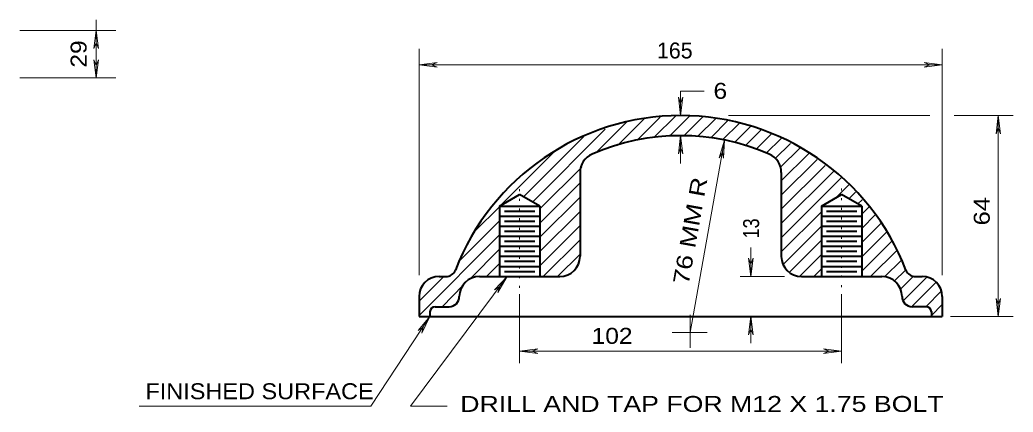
# Model space of a CAD drawing. Extents: x 312583 to 312853, y 144419 to 144586.
# Drawn here: x 312716.88 to 312764.18, y 144532.45 to 144551.14 of the extents above; entities that cross this region are included whole.
import ezdxf

# ---------------------------------------------------------------- set-up
doc = ezdxf.new("R2010")
doc.units = 0
doc.header["$LTSCALE"] = 0.3
doc.linetypes.add('DOTTED', pattern=[1.5, 0.3, -1.2])
doc.layers.add('1', color=7, linetype='Continuous', lineweight=40)
doc.layers.add('2', color=7, linetype='Continuous', lineweight=13)

msp = doc.modelspace()

# ---------------------------------------------------------------- linework, layer by layer
at = {"layer": '1'}
for p, q in [((312743.5539, 144543.8639), (312743.5539, 144539.8773)), ((312753.1372, 144543.8639), (312753.1372, 144539.8773)), ((312739.7205, 144542.2693), (312740.6789, 144542.8213)), ((312741.6372, 144542.2693), (312740.6789, 144542.8213)), ((312755.0539, 144542.2693), (312756.0122, 144542.8213)), ((312756.9705, 144542.2693), (312756.0122, 144542.8213)), ((312739.7205, 144542.2693), (312739.7205, 144538.9189)), ((312739.7205, 144542.2693), (312741.6372, 144542.2693)), ((312741.6372, 144542.2693), (312741.6372, 144538.9189)), ((312755.0539, 144542.2693), (312755.0539, 144538.9189)), ((312755.0539, 144542.2693), (312756.9705, 144542.2693)), ((312756.9705, 144542.2693), (312756.9705, 144538.9189)), ((312739.7205, 144541.7939), (312741.6372, 144541.7939)), ((312739.9582, 144542.0316), (312741.3995, 144542.0316)), ((312755.0539, 144541.7939), (312756.9705, 144541.7939)), ((312755.2915, 144542.0316), (312756.7329, 144542.0316)), ((312739.7205, 144541.3109), (312741.6372, 144541.3109)), ((312739.9582, 144541.5563), (312741.3995, 144541.5563)), ((312755.0539, 144541.3109), (312756.9705, 144541.3109)), ((312755.2915, 144541.5563), (312756.7329, 144541.5563)), ((312739.7205, 144540.8356), (312741.6372, 144540.8356)), ((312739.9582, 144541.0733), (312741.3995, 144541.0733)), ((312755.0539, 144540.8356), (312756.9705, 144540.8356)), ((312755.2915, 144541.0733), (312756.7329, 144541.0733)), ((312739.7205, 144540.3526), (312741.6372, 144540.3526)), ((312739.9582, 144540.5979), (312741.3995, 144540.5979)), ((312755.0539, 144540.3526), (312756.9705, 144540.3526)), ((312755.2915, 144540.5979), (312756.7329, 144540.5979)), ((312739.9582, 144540.1149), (312741.3995, 144540.1149)), ((312755.2915, 144540.1149), (312756.7329, 144540.1149)), ((312739.7205, 144539.8773), (312741.6372, 144539.8773)), ((312739.9582, 144539.6396), (312741.3995, 144539.6396)), ((312755.0539, 144539.8773), (312756.9705, 144539.8773)), ((312755.2915, 144539.6396), (312756.7329, 144539.6396)), ((312739.7205, 144539.3943), (312741.6372, 144539.3943)), ((312739.9582, 144539.1566), (312741.3995, 144539.1566)), ((312755.0539, 144539.3943), (312756.9705, 144539.3943)), ((312755.2915, 144539.1566), (312756.7329, 144539.1566)), ((312736.8455, 144538.9189), (312737.1752, 144538.9189)), ((312738.7622, 144538.9189), (312742.5955, 144538.9189)), ((312754.0955, 144538.9189), (312757.9289, 144538.9189)), ((312759.5235, 144538.9189), (312759.8455, 144538.9189)), ((312735.8872, 144537.9606), (312735.8872, 144537.0023)), ((312760.8039, 144537.9606), (312760.8039, 144537.0023)), ((312736.4085, 144537.2399), (312736.4085, 144537.0023)), ((312736.6539, 144537.4776), (312737.3285, 144537.4776)), ((312760.0449, 144537.4776), (312759.3702, 144537.4776)), ((312760.2825, 144537.2399), (312760.2825, 144537.0023)), ((312735.8872, 144537.0023), (312760.8039, 144537.0023))]:
    msp.add_line(p, q, dxfattribs=at)
at = {"layer": '1', "linetype": 'DOTTED', "lineweight": 13}
for p, q in [((312740.6789, 144543.0743), (312740.6789, 144538.0756)), ((312756.0122, 144543.1049), (312756.0122, 144538.0756))]:
    msp.add_line(p, q, dxfattribs=at)
at = {"layer": '1'}
for centre, radius, start, end in [((312748.3455, 144535.0818), 11.5, 21.1002, 158.90079), ((312748.3455, 144535.0818), 10.5417, 66.41835, 113.58165), ((312744.5122, 144543.865), 0.9583, 113.57818, 180), ((312752.1789, 144543.865), 0.9583, 0, 66.42182), ((312742.5955, 144539.8734), 0.9583, 270, 0), ((312754.0955, 144539.8734), 0.9583, 180, 270), ((312737.1695, 144539.3943), 0.4792, 270, 338.8998), ((312759.5215, 144539.3943), 0.4792, 201.1002, 270), ((312736.8455, 144537.9568), 0.9583, 90, 180), ((312738.7622, 144537.9568), 0.9583, 90, 180), ((312757.9289, 144537.9568), 0.9583, 0, 90), ((312759.8455, 144537.9568), 0.9583, 0, 90), ((312737.3247, 144537.9568), 0.4792, 270, 0), ((312759.3664, 144537.9568), 0.4792, 180, 270), ((312736.6481, 144537.238), 0.2396, 90, 180), ((312760.043, 144537.238), 0.2396, 0, 90)]:
    msp.add_arc(centre, radius, start, end, dxfattribs=at)
at = {"layer": '2'}
for p, q in [((312720.5135, 144548.3759), (312720.5135, 144551.1436)), ((312716.8795, 144550.6376), (312721.4565, 144550.6376)), ((312720.5135, 144550.6376), (312720.4062, 144549.7713)), ((312720.5135, 144550.6376), (312720.6208, 144549.7713)), ((312720.4062, 144549.7713), (312720.5135, 144550.0473)), ((312720.6208, 144549.7713), (312720.5135, 144550.0473)), ((312735.8872, 144538.9803), (312735.8872, 144549.7673)), ((312760.8039, 144538.9803), (312760.8039, 144549.7673)), ((312720.4062, 144549.2423), (312720.5135, 144548.9663)), ((312720.5135, 144548.3759), (312720.4062, 144549.2423)), ((312720.6208, 144549.2423), (312720.5135, 144548.9663)), ((312720.5135, 144548.3759), (312720.6208, 144549.2423)), ((312735.8872, 144549.0006), (312736.7535, 144549.1079)), ((312735.8872, 144549.0006), (312760.8039, 144549.0006)), ((312735.8872, 144549.0006), (312736.7535, 144548.8933)), ((312736.7535, 144549.1079), (312736.4775, 144549.0006)), ((312736.7535, 144548.8933), (312736.4775, 144549.0006)), ((312759.9375, 144549.1079), (312760.2135, 144549.0006)), ((312760.8039, 144549.0006), (312759.9375, 144549.1079)), ((312759.9375, 144548.8933), (312760.2135, 144549.0006)), ((312760.8039, 144549.0006), (312759.9375, 144548.8933)), ((312716.8795, 144548.3759), (312721.4565, 144548.3759)), ((312748.2382, 144547.4519), (312748.3455, 144547.1759)), ((312748.3455, 144546.5856), (312748.2382, 144547.4519)), ((312748.3455, 144547.7509), (312749.4725, 144547.7509)), ((312748.3455, 144546.5856), (312748.3455, 144547.7509)), ((312748.4529, 144547.4519), (312748.3455, 144547.1759)), ((312748.3455, 144546.5856), (312748.4529, 144547.4519)), ((312746.2832, 144545.4203), (312747.3719, 144546.5089)), ((312747.0882, 144545.5506), (312748.1079, 144546.5703)), ((312747.8319, 144545.6119), (312748.7672, 144546.5549)), ((312748.5142, 144545.6273), (312749.3882, 144546.5013)), ((312750.6302, 144546.5856), (312760.2059, 144546.5856)), ((312761.3635, 144546.5856), (312764.1772, 144546.5856)), ((312763.4719, 144546.5856), (312763.3645, 144545.7193)), ((312763.4719, 144537.0023), (312763.4719, 144546.5856)), ((312763.4719, 144546.5856), (312763.5792, 144545.7193)), ((312744.3129, 144544.8069), (312745.7772, 144546.2789)), ((312745.3402, 144545.1596), (312746.6359, 144546.4553)), ((312749.1659, 144545.5966), (312750.0169, 144546.4476)), ((312749.7792, 144545.5276), (312750.5919, 144546.3479)), ((312750.3542, 144545.4356), (312751.1285, 144546.2023)), ((312750.9062, 144545.2976), (312751.6652, 144546.0566)), ((312740.8629, 144542.7139), (312743.7379, 144545.5889)), ((312741.2999, 144542.4686), (312744.7575, 144545.9339)), ((312748.3455, 144545.6273), (312748.2382, 144544.7609)), ((312748.3455, 144544.2933), (312748.3455, 144545.6273)), ((312748.3455, 144545.6273), (312748.4529, 144544.7609)), ((312751.4199, 144545.1443), (312752.1942, 144545.9186)), ((312751.9259, 144544.9679), (312752.6772, 144545.7193)), ((312763.3645, 144545.7193), (312763.4719, 144545.9953)), ((312763.5792, 144545.7193), (312763.4719, 144545.9953)), ((312748.8055, 144536.2509), (312750.4385, 144545.4126)), ((312750.4385, 144545.4126), (312750.1855, 144544.5769)), ((312750.4385, 144545.4126), (312750.3925, 144544.5463)), ((312752.4242, 144544.7916), (312753.1295, 144545.4893)), ((312752.8382, 144544.5309), (312753.5742, 144545.2593)), ((312739.7742, 144542.2999), (312742.3809, 144544.9143)), ((312748.2382, 144544.7609), (312748.3455, 144545.0369)), ((312748.4529, 144544.7609), (312748.3455, 144545.0369)), ((312750.1855, 144544.5769), (312750.3389, 144544.8299)), ((312750.3925, 144544.5463), (312750.3389, 144544.8299)), ((312753.1065, 144544.1169), (312754.0265, 144545.0293)), ((312753.1372, 144543.4729), (312754.4482, 144544.7763)), ((312753.1372, 144542.7906), (312754.8392, 144544.4926)), ((312753.1372, 144542.1159), (312755.2302, 144544.2089)), ((312741.6449, 144542.1389), (312743.6382, 144544.1323)), ((312753.1372, 144541.4413), (312755.6289, 144543.9253)), ((312741.6449, 144541.4566), (312743.5539, 144543.3733)), ((312753.1372, 144540.7589), (312756.0199, 144543.6416)), ((312755.6979, 144542.6373), (312756.3495, 144543.2889)), ((312756.3572, 144542.6219), (312756.6715, 144542.9363)), ((312738.5399, 144541.0733), (312739.7282, 144542.2539)), ((312741.6449, 144540.7819), (312743.5539, 144542.6986)), ((312756.7865, 144542.3766), (312756.9859, 144542.5759)), ((312741.6449, 144540.1073), (312743.5539, 144542.0163)), ((312753.1372, 144540.0843), (312755.0539, 144541.9933)), ((312756.9705, 144541.8859), (312757.3079, 144542.2156)), ((312756.9705, 144541.2036), (312757.6299, 144541.8629)), ((312737.8422, 144539.6933), (312739.7205, 144541.5716)), ((312741.6449, 144539.4249), (312743.5539, 144541.3416)), ((312753.2599, 144539.5246), (312755.0539, 144541.3186)), ((312756.9705, 144540.5289), (312757.8905, 144541.4489)), ((312735.8872, 144537.0636), (312739.7205, 144540.8969)), ((312756.9705, 144539.8466), (312758.1512, 144541.0273)), ((312741.8059, 144538.9189), (312743.5539, 144540.6593)), ((312753.5512, 144539.1336), (312755.0539, 144540.6439)), ((312756.9705, 144539.1719), (312758.4042, 144540.5979)), ((312738.3175, 144538.8116), (312739.7205, 144540.2146)), ((312742.4882, 144538.9189), (312743.5539, 144539.9846)), ((312751.6882, 144538.9189), (312751.6882, 144540.2913)), ((312754.0342, 144538.9419), (312755.0539, 144539.9616)), ((312757.3922, 144538.9189), (312758.6495, 144540.1763)), ((312739.0995, 144538.9189), (312739.7205, 144539.5399)), ((312751.5809, 144539.7853), (312751.6882, 144539.5093)), ((312751.6882, 144538.9189), (312751.5809, 144539.7853)), ((312751.7955, 144539.7853), (312751.6882, 144539.5093)), ((312751.6882, 144538.9189), (312751.7955, 144539.7853)), ((312758.0439, 144538.8883), (312758.8719, 144539.7163)), ((312754.6859, 144538.9189), (312755.0539, 144539.2869)), ((312758.5039, 144538.6736), (312759.0712, 144539.2333)), ((312758.8029, 144538.2903), (312759.4469, 144538.9419)), ((312735.4732, 144532.7319), (312740.0809, 144538.9189)), ((312735.8872, 144537.7383), (312737.0449, 144538.8959)), ((312736.9835, 144537.4776), (312737.9955, 144538.4973)), ((312740.0809, 144538.9189), (312739.4752, 144538.2826)), ((312740.0809, 144538.9189), (312739.6439, 144538.1599)), ((312753.2829, 144538.9189), (312751.1745, 144538.9189)), ((312758.9792, 144537.7843), (312760.0679, 144538.8806)), ((312759.3549, 144537.4853), (312760.5355, 144538.6659)), ((312739.4752, 144538.2826), (312739.7282, 144538.4436)), ((312739.6439, 144538.1599), (312739.7282, 144538.4436)), ((312740.6789, 144538.0756), (312740.6789, 144534.7789)), ((312756.0122, 144538.0756), (312756.0122, 144534.7789)), ((312760.0219, 144537.4776), (312760.7732, 144538.2289)), ((312760.2825, 144537.0636), (312760.8039, 144537.5849)), ((312763.3645, 144537.8686), (312763.4719, 144537.5926)), ((312763.4719, 144537.0023), (312763.3645, 144537.8686)), ((312763.5792, 144537.8686), (312763.4719, 144537.5926)), ((312763.4719, 144537.0023), (312763.5792, 144537.8686)), ((312748.7979, 144535.5149), (312748.7979, 144537.0866)), ((312736.4085, 144537.0023), (312733.5872, 144532.7319)), ((312736.4085, 144537.0023), (312735.8412, 144536.3353)), ((312736.4085, 144537.0023), (312736.0252, 144536.2203)), ((312751.6882, 144537.0023), (312751.5809, 144536.1359)), ((312751.6882, 144537.0023), (312751.7955, 144536.1359)), ((312751.6882, 144535.7373), (312751.6882, 144537.0023)), ((312761.1949, 144537.0023), (312764.1772, 144537.0023)), ((312735.8412, 144536.3353), (312736.0865, 144536.5039)), ((312736.0252, 144536.2203), (312736.0865, 144536.5039)), ((312747.9392, 144536.2509), (312749.6029, 144536.2509)), ((312751.5809, 144536.1359), (312751.6882, 144536.4119)), ((312751.7955, 144536.1359), (312751.6882, 144536.4119)), ((312740.6789, 144535.3539), (312741.5452, 144535.4613)), ((312740.6789, 144535.3539), (312756.0122, 144535.3539)), ((312740.6789, 144535.3539), (312741.5452, 144535.2466)), ((312741.5452, 144535.4613), (312741.2692, 144535.3539)), ((312741.5452, 144535.2466), (312741.2692, 144535.3539)), ((312755.1459, 144535.4613), (312755.4219, 144535.3539)), ((312756.0122, 144535.3539), (312755.1459, 144535.4613)), ((312755.1459, 144535.2466), (312755.4219, 144535.3539)), ((312756.0122, 144535.3539), (312755.1459, 144535.2466)), ((312733.5872, 144532.7319), (312722.5656, 144532.7319)), ((312737.2212, 144532.7319), (312735.4732, 144532.7319))]:
    msp.add_line(p, q, dxfattribs=at)

# ---------------------------------------------------------------- texts
for s, rotation, width, p in [('29 ', 90, 1.15, (312720.0571, 144548.8683)), ('76 MM R', 79.87, 1.25, (312748.7199, 144538.4918)), ('64 ', 90, 1.2, (312763.0631, 144541.3477)), ('13', 90, 0.85, (312752.0812, 144540.7245))]:
    msp.add_text(s, height=0.76, rotation=rotation, dxfattribs=dict(at, width=width)).set_placement(p)
msp.add_text('165', height=0.76, dxfattribs=at).set_placement((312747.2186, 144549.3034))
for s, width, p in [('6 ', 1.15, (312749.9088, 144547.381)), ('102 ', 1.15, (312744.1037, 144535.7066)), ('FINISHED SURFACE', 1.1, (312722.8574, 144533.0683)), ('DRILL AND TAP FOR M12 X 1.75 BOLT', 1.25, (312737.8499, 144532.4626))]:
    msp.add_text(s, height=0.76, dxfattribs=dict(at, width=width)).set_placement(p)

doc.saveas('drawing.dxf')
